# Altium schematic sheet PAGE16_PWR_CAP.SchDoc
size 381 x 381 mm; SheetNumber: 17; SheetTotal: 28
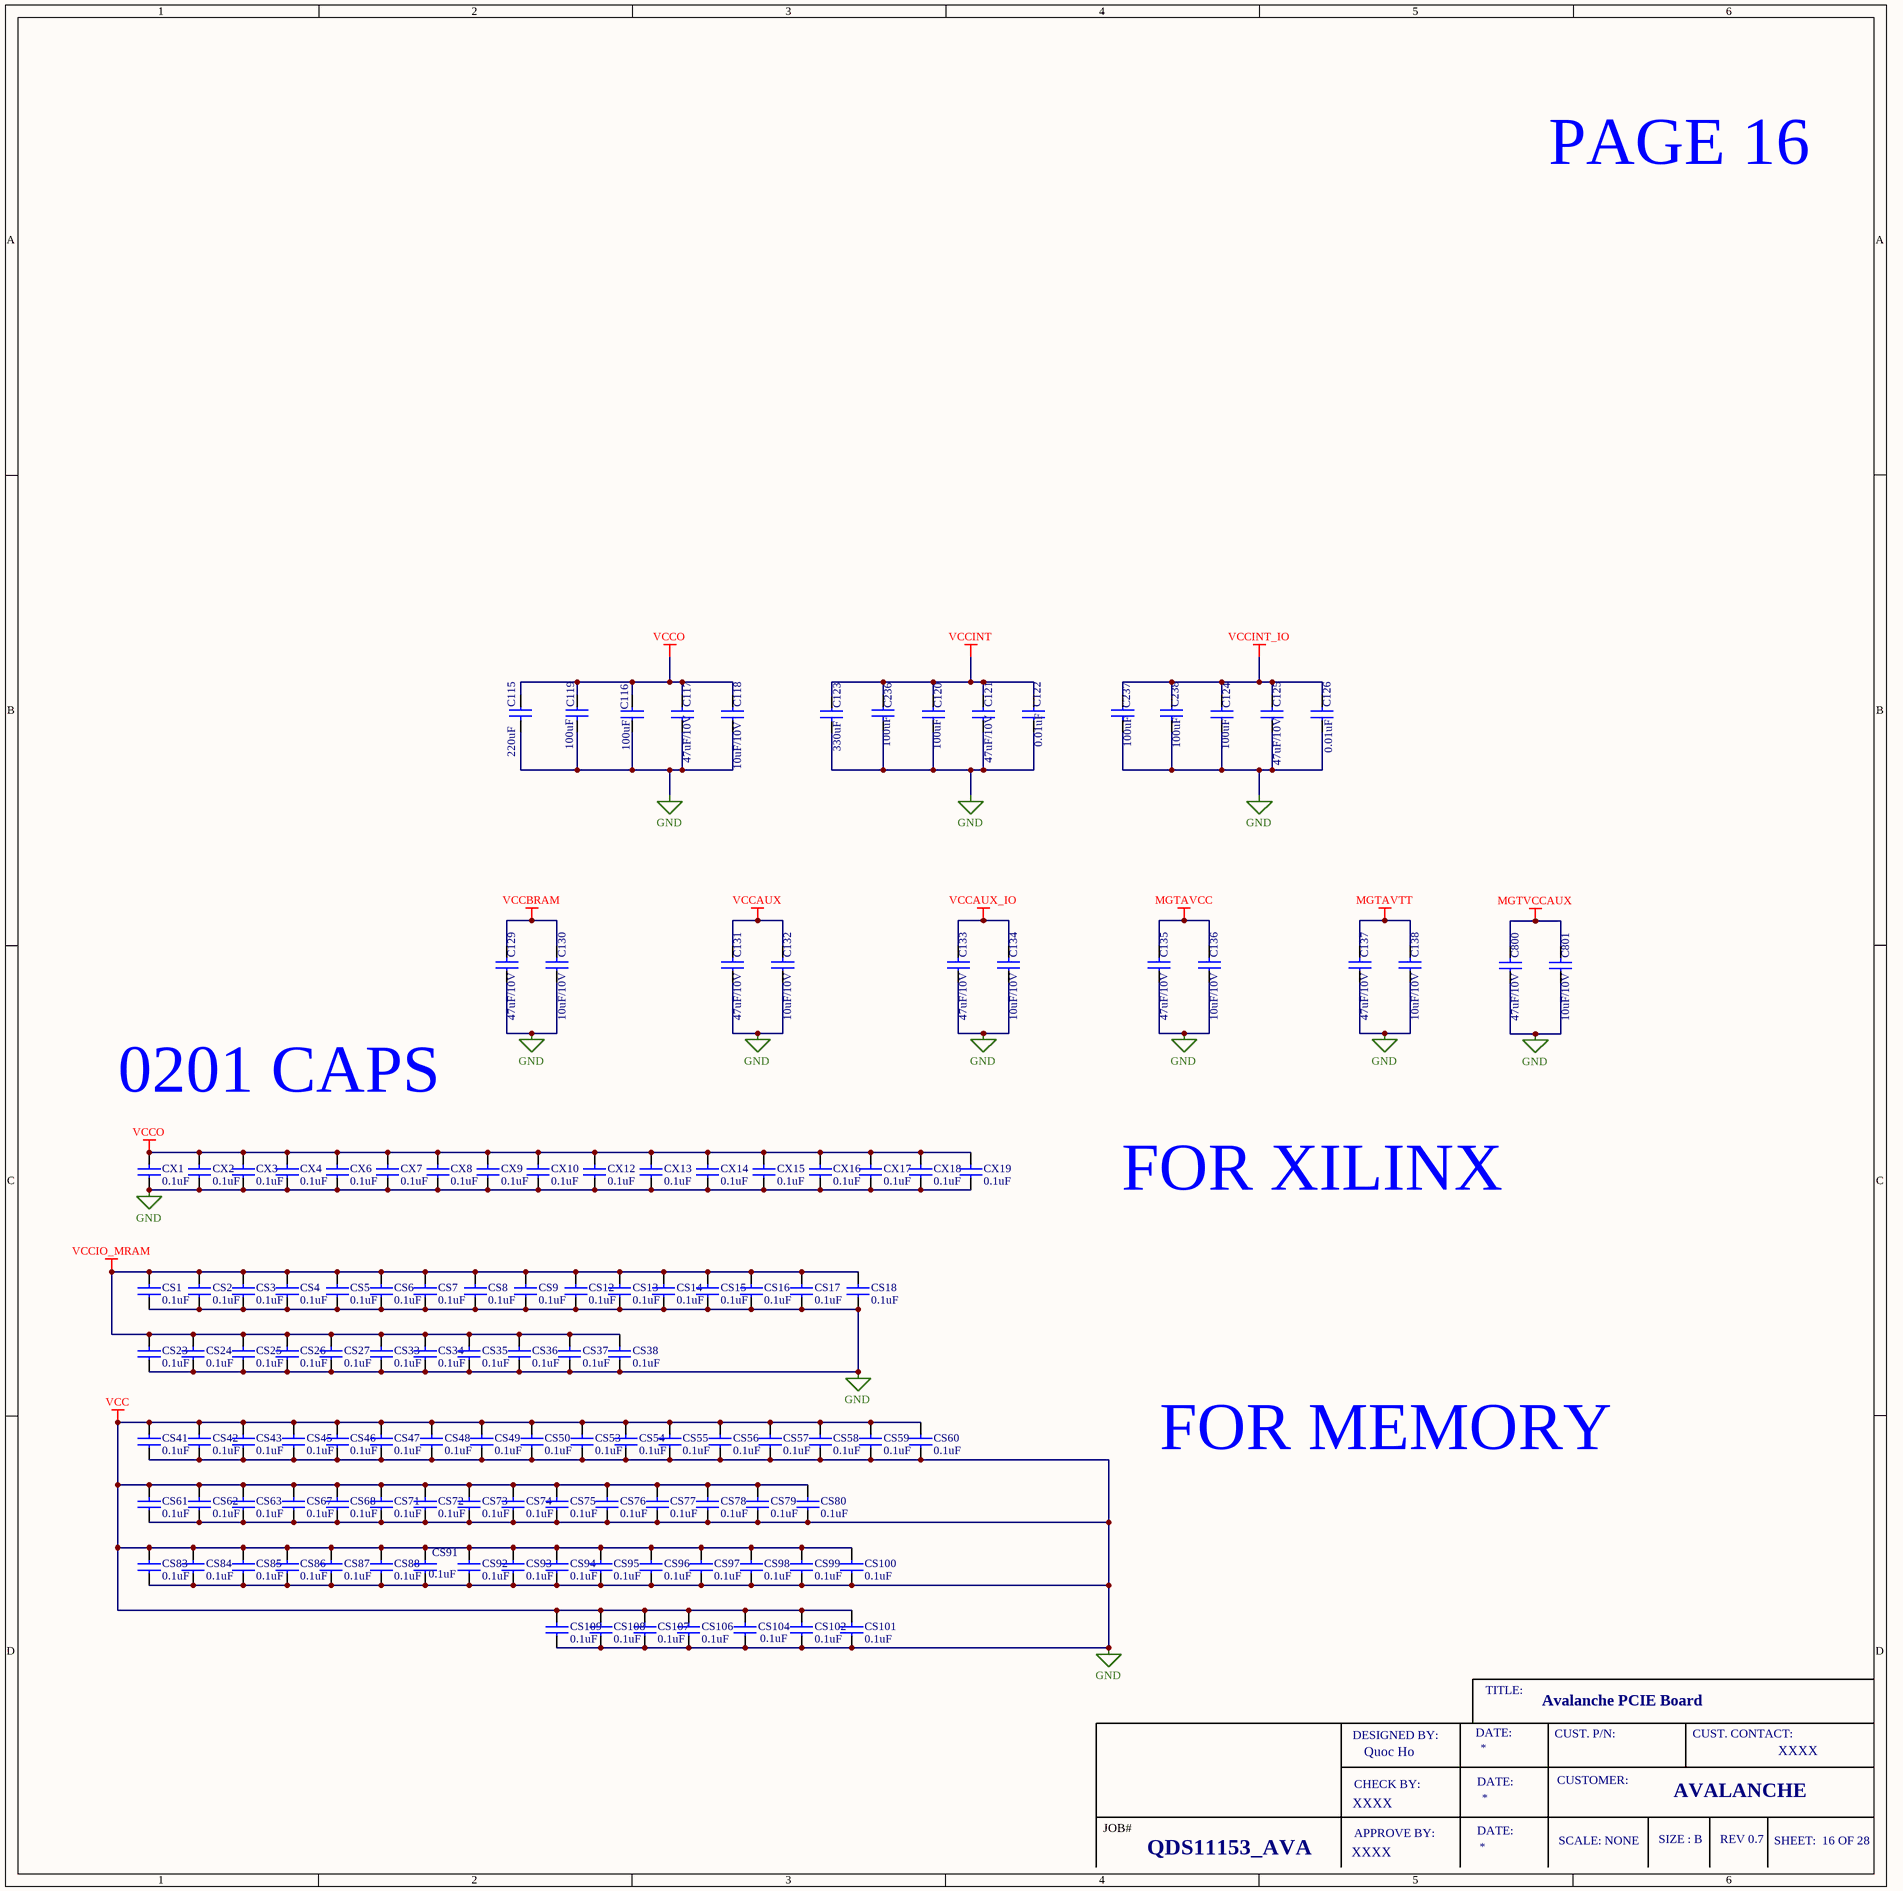
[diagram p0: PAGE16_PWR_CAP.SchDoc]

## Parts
C115  220uF  [CN_1206]
C116  100uF  [CN_1206]
C117  47uF/10V  [CN_0805]
C118  10uF/10V  [CN_0402]
C119  100uF  [CN_1206]
C120  100uF  [CN_1206]
C121  47uF/10V  [CN_0805]
C122  0.01uF  [CN_0402]
C123  330uF  [CN_1210]
C124  100uF  [CN_1206]
C125  47uF/10V  [CN_0805]
C126  0.01uF  [CN_0402]
C129  47uF/10V  [CN_0805]
C130  10uF/10V  [CN_0402]
C131  47uF/10V  [CN_0805]
C132  10uF/10V  [CN_0402]
C133  47uF/10V  [CN_0805]
C134  10uF/10V  [CN_0402]
C135  47uF/10V  [CN_0805]
C136  10uF/10V  [CN_0402]
C137  47uF/10V  [CN_0805]
C138  10uF/10V  [CN_0402]
C236  100uF  [CN_1206]
C237  100uF  [CN_1206]
C238  100uF  [CN_1206]
C800  47uF/10V  [CN_0805]
C801  10uF/10V  [CN_0402]
CS1  0.1uF  [CN_0201]
CS2  0.1uF  [CN_0201]
CS3  0.1uF  [CN_0201]
CS4  0.1uF  [CN_0201]
CS5  0.1uF  [CN_0201]
CS6  0.1uF  [CN_0201]
CS7  0.1uF  [CN_0201]
CS8  0.1uF  [CN_0201]
CS9  0.1uF  [CN_0201]
CS12  0.1uF  [CN_0201]
CS13  0.1uF  [CN_0201]
CS14  0.1uF  [CN_0201]
CS15  0.1uF  [CN_0201]
CS16  0.1uF  [CN_0201]
CS17  0.1uF  [CN_0201]
CS18  0.1uF  [CN_0201]
CS23  0.1uF  [CN_0201]
CS24  0.1uF  [CN_0201]
CS25  0.1uF  [CN_0201]
CS26  0.1uF  [CN_0201]
CS27  0.1uF  [CN_0201]
CS33  0.1uF  [CN_0201]
CS34  0.1uF  [CN_0201]
CS35  0.1uF  [CN_0201]
CS36  0.1uF  [CN_0201]
CS37  0.1uF  [CN_0201]
CS38  0.1uF  [CN_0201]
CS41  0.1uF  [CN_0201]
CS42  0.1uF  [CN_0201]
CS43  0.1uF  [CN_0201]
CS45  0.1uF  [CN_0201]
CS46  0.1uF  [CN_0201]
CS47  0.1uF  [CN_0201]
CS48  0.1uF  [CN_0201]
CS49  0.1uF  [CN_0201]
CS50  0.1uF  [CN_0201]
CS53  0.1uF  [CN_0201]
CS54  0.1uF  [CN_0201]
CS55  0.1uF  [CN_0201]
CS56  0.1uF  [CN_0201]
CS57  0.1uF  [CN_0201]
CS58  0.1uF  [CN_0201]
CS59  0.1uF  [CN_0201]
CS60  0.1uF  [CN_0201]
CS61  0.1uF  [CN_0201]
CS62  0.1uF  [CN_0201]
CS63  0.1uF  [CN_0201]
CS67  0.1uF  [CN_0201]
CS68  0.1uF  [CN_0201]
CS71  0.1uF  [CN_0201]
CS72  0.1uF  [CN_0201]
CS73  0.1uF  [CN_0201]
CS74  0.1uF  [CN_0201]
CS75  0.1uF  [CN_0201]
CS76  0.1uF  [CN_0201]
CS77  0.1uF  [CN_0201]
CS78  0.1uF  [CN_0201]
CS79  0.1uF  [CN_0201]
CS80  0.1uF  [CN_0201]
CS83  0.1uF  [CN_0201]
CS84  0.1uF  [CN_0201]
CS85  0.1uF  [CN_0201]
CS86  0.1uF  [CN_0201]
CS87  0.1uF  [CN_0201]
CS88  0.1uF  [CN_0201]
CS91  0.1uF  [CN_0201]
CS92  0.1uF  [CN_0201]
CS93  0.1uF  [CN_0201]
CS94  0.1uF  [CN_0201]
CS95  0.1uF  [CN_0201]
CS96  0.1uF  [CN_0201]
CS97  0.1uF  [CN_0201]
CS98  0.1uF  [CN_0201]
CS99  0.1uF  [CN_0201]
CS100  0.1uF  [CN_0201]
CS101  0.1uF  [CN_0201]
CS102  0.1uF  [CN_0201]
CS104  0.1uF  [CN_0201]
CS106  0.1uF  [CN_0201]
CS107  0.1uF  [CN_0201]
CS108  0.1uF  [CN_0201]
CS109  0.1uF  [CN_0201]
CX1  0.1uF  [CN_0201]
CX2  0.1uF  [CN_0201]
CX3  0.1uF  [CN_0201]
CX4  0.1uF  [CN_0201]
CX6  0.1uF  [CN_0201]
CX7  0.1uF  [CN_0201]
CX8  0.1uF  [CN_0201]
CX9  0.1uF  [CN_0201]
CX10  0.1uF  [CN_0201]
CX12  0.1uF  [CN_0201]
CX13  0.1uF  [CN_0201]
CX14  0.1uF  [CN_0201]
CX15  0.1uF  [CN_0201]
CX16  0.1uF  [CN_0201]
CX17  0.1uF  [CN_0201]
CX18  0.1uF  [CN_0201]
CX19  0.1uF  [CN_0201]

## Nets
GND: C115.2 C116.1 C117.1 C118.1 C119.2 C120.1 C121.1 C122.1 C123.2 C124.1 C125.1 C126.1 C129.1 C130.1 C131.1 C132.1 C133.1 C134.1 C135.1 C136.1 C137.1 C138.1 C236.2 C237.2 C238.2 C800.1 C801.1 CS1.1 CS2.1 CS3.1 CS4.1 CS5.1 CS6.1 CS7.1 CS8.1 CS9.1 CS12.1 CS13.1 CS14.1 CS15.1 CS16.1 CS17.1 CS18.1 CS23.1 CS24.1 CS25.1 CS26.1 CS27.1 CS33.1 CS34.1 CS35.1 CS36.1 CS37.1 CS38.1 CS41.1 CS42.1 CS43.1 CS45.1 CS46.1 CS47.1 CS48.1 CS49.1 CS50.1 CS53.1 CS54.1 CS55.1 CS56.1 CS57.1 CS58.1 CS59.1 CS60.1 CS61.1 CS62.1 CS63.1 CS67.1 CS68.1 CS71.1 CS72.1 CS73.1 CS74.1 CS75.1 CS76.1 CS77.1 CS78.1 CS79.1 CS80.1 CS83.1 CS84.1 CS85.1 CS86.1 CS87.1 CS88.1 CS91.1 CS92.1 CS93.1 CS94.1 CS95.1 CS96.1 CS97.1 CS98.1 CS99.1 CS100.1 CS101.1 CS102.1 CS104.1 CS106.1 CS107.1 CS108.1 CS109.1 CX1.1 CX2.1 CX3.1 CX4.1 CX6.1 CX7.1 CX8.1 CX9.1 CX10.1 CX12.1 CX13.1 CX14.1 CX15.1 CX16.1 CX17.1 CX18.1 CX19.1
MGTAVCC: C135.2 C136.2
MGTAVTT: C137.2 C138.2
MGTVCCAUX: C800.2 C801.2
VCC: CS41.2 CS42.2 CS43.2 CS45.2 CS46.2 CS47.2 CS48.2 CS49.2 CS50.2 CS53.2 CS54.2 CS55.2 CS56.2 CS57.2 CS58.2 CS59.2 CS60.2 CS61.2 CS62.2 CS63.2 CS67.2 CS68.2 CS71.2 CS72.2 CS73.2 CS74.2 CS75.2 CS76.2 CS77.2 CS78.2 CS79.2 CS80.2 CS83.2 CS84.2 CS85.2 CS86.2 CS87.2 CS88.2 CS91.2 CS92.2 CS93.2 CS94.2 CS95.2 CS96.2 CS97.2 CS98.2 CS99.2 CS100.2 CS101.2 CS102.2 CS104.2 CS106.2 CS107.2 CS108.2 CS109.2
VCCAUX: C131.2 C132.2
VCCAUX_IO: C133.2 C134.2
VCCBRAM: C129.2 C130.2
VCCINT: C120.2 C121.2 C122.2 C123.1 C236.1
VCCINT_IO: C124.2 C125.2 C126.2 C237.1 C238.1
VCCIO_MRAM: CS1.2 CS2.2 CS3.2 CS4.2 CS5.2 CS6.2 CS7.2 CS8.2 CS9.2 CS12.2 CS13.2 CS14.2 CS15.2 CS16.2 CS17.2 CS18.2 CS23.2 CS24.2 CS25.2 CS26.2 CS27.2 CS33.2 CS34.2 CS35.2 CS36.2 CS37.2 CS38.2
VCCO: C115.1 C116.2 C117.2 C118.2 C119.1 CX1.2 CX2.2 CX3.2 CX4.2 CX6.2 CX7.2 CX8.2 CX9.2 CX10.2 CX12.2 CX13.2 CX14.2 CX15.2 CX16.2 CX17.2 CX18.2 CX19.2

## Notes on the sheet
- PAGE 16
- 0201 CAPS
- FOR XILINX
- FOR MEMORY
- TITLE:
- Avalanche PCIE Board
- DESIGNED BY:
- CHECK BY:
- Quoc Ho
- DATE:
- CUST. P/N:
- CUSTOMER:
- CUST. CONTACT:
- XXXX
- JOB#
- APPROVE BY:
- SCALE: NONE
- SIZE : B
- AVALANCHE
- REV 0.7
- SHEET:  16 OF 28
- QDS11153_AVA

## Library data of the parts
C115 = CAP: CAP CER 220UF 6.3V X5R 1206; Manufacturer Part Number: GRM31CR60J227ME11K; Manufacturer: Murata Electronics
C116 C237 C238 = CAP: CAP CER 100UF 10V X5R 1206; Manufacturer: Murata Electronics; Manufacturer Part Number: GRM31CR61A107MEA8L
C117 C125 C129 C131 C133 C135 C137 C800 = CAP: CAP CER 47UF 10V X5R 0805; Manufacturer Part Number: GRM21BR61A476ME15K; Manufacturer: Murata Electronics
C118 C130 C132 C134 C136 C138 C801 = CAP: CAP CER 10UF 10V X5R 0402; Manufacturer Part Number: GRM155R61A106ME11D; Manufacturer: Murata Electronics
C119 C120 C124 C236 = CAP: CAP CER 100UF 10V X5R 1206; Manufacturer Part Number: GRM31CR61A107MEA8L; Manufacturer: Murata Electronics
C121 = CAP: CAP CER 47UF 10V X5R 0805; Manufacturer: Murata Electronics; Manufacturer Part Number: GRM21BR61A476ME15K
C122 C126 = CAP: 0.01 µF, 25 V, 0402 [1005 Metric], ± 10%, X7R; Manufacturer: YAGEO; Manufacturer Part Number: CC0402JRX7R8BB103
C123 = CAP: CAP CER 330UF 6.3V X5R 1210 20%; Manufacturer Part Number: JMK325ABJ337MM-PE; Manufacturer: TAIYO YUDEN
CS1-CS9 CS12-CS18 CS23-CS27 CS33-CS38 CS41-CS43 CS45-CS50 CS53-CS63 CS67 CS68 CS71-CS80 CS91 CX1-CX4 CX6-CX10 CX12-CX19 = CAP: CAP CER 0.1UF 35V X5R 0201; Manufacturer Part Number: GRM033R6YA104KE14D; Manufacturer: Murata Electronics
CS83-CS88 CS92-CS102 CS104 CS106-CS109 = CAP: CAP CER 0.1UF 35V X5R 0201; Manufacturer: Murata Electronics; Manufacturer Part Number: GRM033R6YA104KE14D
